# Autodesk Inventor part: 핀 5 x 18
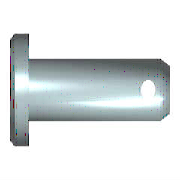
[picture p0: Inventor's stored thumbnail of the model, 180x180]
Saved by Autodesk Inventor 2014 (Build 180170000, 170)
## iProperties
Created: 2012-02
Part Number: 핀 5 x 18
Material: 강철
Description: 머리가 있는 클레비스 핀
Document SubType Name: Modeling
Standard: ISO 2341
Designer: test
Standard Revision: Second edition 1986-11-01
Standards Organization: ISO
Language: ko-KR
Size Designation: B - 5 x 18
Categories: <MemberInstance><Categories><Category DisplayName="조임쇠" InternalName="e4da775c-781d-43d5-af7c-5136215cf5a6" Mnemonic="FSTN"><Category DisplayName="핀" InternalNa
Density: 7.85 g/cm^3
Appearance: Steel
IsCustomPart: 1
Author: test
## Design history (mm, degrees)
sketch "스케치1"
  geometry: L1 (-1.6, 0)-(-1.6, 4); L2 (-1.6, 4)-(0, 4); L3 (0, 4)-(0, 2.5); L4 (0, 2.5)-(18, 2.5); L5 (18, 2.5)-(18, 0); L6 (-1.6, 0)-(18, 0); L7 (-4, 0)-(17, 0) reference; L8 (0, -0.98)-(0, 3.08) reference; C1 r 0.6 at (15.1, 0)
  constraints: 12 end point, 3 parallel, 2 collinear, 2 perpendicular, 1 centre point, 1 point on line, 1 vertical
  dimensions: "d0" = 5 diameter of L4 L6 (= NND); "d1" = 8 diameter of L2 L6 (= KOD); "d2" = 1.6 distance of L1.end L2.end (= KOH); "d3" = 18 distance of L3.end L4.end (= NLG); "d5" = 2.9 distance from line of L5 C1.centre (= DIST); "d6" = 1.2 diameter of C1 (= BOR)
revolve "본체" stored, may be unused: angle "d4" = 90 deg
extrude "구멍" cut sketch "스케치1" stored distance "d7" = 5 (= NND); taper "d8" = 0 deg
body "Solid1"
chamfer "모따기1" distance "d9" = 1 (= PHH2); stored, may be unused: angle "d10" = 45 deg (= FAWI2), second distance "d16" = 1 (= PHH2)
chamfer "모따기2" distance "d11" = 2 (= PHH1); stored, may be unused: angle "d12" = 30 deg (= FAWI1), second distance "d17" = 2 (= PHH1)
workaxis "Work Axis1"
workplane "Work Plane1"
other parameters: "PHH1" = 2 [user parameter; used in 2 equation terms], "PHH2" = 1 [user parameter; used in 2 equation terms], "KOD" = 8 [user parameter; used in 1 equation term], "KOH" = 1.6 [user parameter; used in 1 equation term], "NND" = 5 [user parameter; used in 2 equation terms], "FAWI1" = 30 deg [user parameter; used in 1 equation term], "FAWI2" = 45 deg [user parameter; used in 1 equation term], "DIST" = 2.9 [user parameter; used in 1 equation term], "BOR" = 1.2 [user parameter; used in 1 equation term], "NLG" = 18 [user parameter; used in 1 equation term], "d13" = 0, "d14" = 0, "d27" = 0, "d28" = 0, "d29" = 0, "d30" = 0, "d31" = 0
